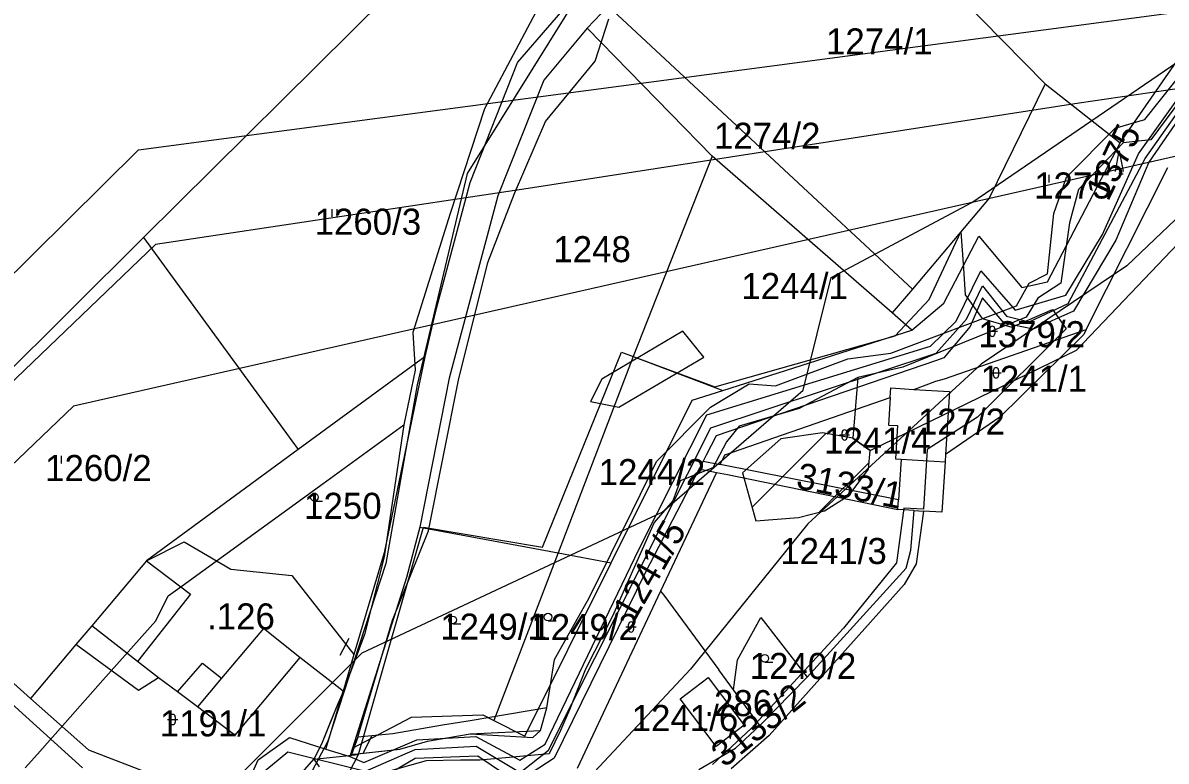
# Model space of a CAD drawing. Extents: x -564810 to -550519, y -1045831 to -1034011.
# Drawn here: x -554205.9 to -553982, y -1038887.8 to -1038743.2 of the extents above; entities that cross this region are included whole.
import ezdxf

# ---------------------------------------------------------------- set-up
doc = ezdxf.new("R2010")
doc.units = 0
for name, color, linetype in [('KN stav', 7, 'Continuous'), ('Lesní porost', 7, 'Continuous'), ('Obvod KPU', 7, 'Continuous'), ('Parcelní čísla', 7, 'Continuous'), ('Polní cesty stavající', 7, 'Continuous'), ('STG', 7, 'Continuous'), ('Vedení VN', 7, 'Continuous'), ('Vodní plocha', 7, 'Continuous'), ('vodní toky', 7, 'Continuous'), ('Vrstva 22', 7, 'Continuous'), ('Vrstva 33', 7, 'Continuous'), ('Vrstva 39', 7, 'Continuous'), ('Vrstva 4', 7, 'Continuous'), ('zamokř ploch', 7, 'Continuous')]:
    doc.layers.add(name, color=color, linetype=linetype)

msp = doc.modelspace()

# ---------------------------------------------------------------- linework, layer by layer
at = {"layer": 'KN stav'}
for p, q in [((-554056.62, -1038703.41), (-554005.71, -1038755.12)), ((-554115.3, -1038718.86), (-554182.27, -1038785.24)), ((-554099.39, -1038739.76), (-554109.03, -1038750.89)), ((-554091.3, -1038739.91), (-554095.38, -1038744.23)), ((-554091.3, -1038739.91), (-554031.72, -1038795.33)), ((-554095.38, -1038744.23), (-554103.88, -1038754.42)), ((-554095.38, -1038744.23), (-554070.95, -1038769.33)), ((-553987.46, -1038768.82), (-553971.66, -1038746.69)), ((-553969.78, -1038747.75), (-553985.45, -1038770.47)), ((-553991.06, -1038766.69), (-553978.32, -1038748.33)), ((-554109.03, -1038750.89), (-554118.37, -1038774.51)), ((-554103.88, -1038754.42), (-554112.89, -1038777.05)), ((-554005.71, -1038755.12), (-554016.72, -1038777.54)), ((-554005.71, -1038755.12), (-553991.06, -1038766.69)), ((-554005.27, -1038793.9), (-553991.06, -1038766.69)), ((-554070.95, -1038769.33), (-554086.39, -1038808.52)), ((-554035.67, -1038800.01), (-554070.95, -1038769.33)), ((-553994.51, -1038784.66), (-553987.46, -1038768.82)), ((-553997.71, -1038803.26), (-553981.71, -1038771.49)), ((-553985.45, -1038770.47), (-553991.92, -1038785.77)), ((-554118.37, -1038774.51), (-554125.24, -1038800.17)), ((-554112.89, -1038777.05), (-554122.41, -1038812.76)), ((-554016.72, -1038777.54), (-554031.72, -1038795.33)), ((-554182.27, -1038785.24), (-554239.98, -1038842.52)), ((-554182.27, -1038785.24), (-554151.98, -1038826.75)), ((-554025.55, -1038798.11), (-554018.7, -1038784.97)), ((-554018.7, -1038784.97), (-554010.3, -1038795.05)), ((-554001.65, -1038796.55), (-553994.51, -1038784.66)), ((-553991.92, -1038785.77), (-554000.2, -1038799.65)), ((-554023.15, -1038801.62), (-554018.35, -1038791.75)), ((-554018.35, -1038791.75), (-554011.58, -1038799.45)), ((-554010.3, -1038795.05), (-554005.27, -1038793.9)), ((-554031.72, -1038795.33), (-554035.67, -1038800.01)), ((-554018.03, -1038797.01), (-554020.4, -1038802.67)), ((-554013.75, -1038802.02), (-554018.03, -1038797.01)), ((-554011.58, -1038799.45), (-554001.65, -1038796.55)), ((-554031.82, -1038803.36), (-554025.55, -1038798.11)), ((-554125.24, -1038800.17), (-554127.21, -1038808.6)), ((-554031.82, -1038803.36), (-554035.67, -1038800.01)), ((-554028.15, -1038806.49), (-554023.15, -1038801.62)), ((-554000.2, -1038799.65), (-554008.1, -1038803.2)), ((-554068.84, -1038815.18), (-554031.82, -1038803.36)), ((-554020.4, -1038802.67), (-554025.54, -1038808.81)), ((-554025.44, -1038812.88), (-553997.71, -1038803.26)), ((-554008.1, -1038803.2), (-554013.75, -1038802.02)), ((-553997.71, -1038803.26), (-553998.18, -1038804.2)), ((-553998.18, -1038804.2), (-554014.59, -1038820.44)), ((-554071.99, -1038819.97), (-554028.15, -1038806.49)), ((-554127.21, -1038808.6), (-554151.98, -1038826.75)), ((-554127.21, -1038808.6), (-554135.17, -1038846.98)), ((-554086.39, -1038808.52), (-554101.09, -1038846.95)), ((-554086.39, -1038808.52), (-554071.04, -1038814.34)), ((-554027.18, -1038809.37), (-554070.14, -1038824.05)), ((-554025.54, -1038808.81), (-554027.18, -1038809.37)), ((-554122.41, -1038812.76), (-554128.16, -1038841.93)), ((-554071.04, -1038814.34), (-554068.84, -1038815.18)), ((-554036.08, -1038816.57), (-554035.96, -1038814.67)), ((-554035.96, -1038814.67), (-554031.43, -1038814.96)), ((-554031.43, -1038814.96), (-554027.12, -1038813.37)), ((-554031.43, -1038814.96), (-554024.46, -1038815.39)), ((-554027.12, -1038813.37), (-554025.44, -1038812.88)), ((-554090.71, -1038848.96), (-554074.85, -1038817.1)), ((-554074.85, -1038817.1), (-554068.84, -1038815.18)), ((-554068.47, -1038827.8), (-554036.08, -1038816.57)), ((-554036.08, -1038816.57), (-554036.41, -1038821.95)), ((-554024.46, -1038815.39), (-554025.23, -1038827.74)), ((-554085.24, -1038846.17), (-554071.99, -1038819.97)), ((-554014.59, -1038820.44), (-554025.23, -1038827.74)), ((-554036.41, -1038821.95), (-554034.66, -1038822.06)), ((-554034.66, -1038822.06), (-554035.06, -1038828.57)), ((-554070.14, -1038824.05), (-554072.1, -1038827.84)), ((-554151.98, -1038826.75), (-554181.72, -1038848.55)), ((-554072.1, -1038827.84), (-554072.71, -1038829.01)), ((-554069.35, -1038829.68), (-554068.81, -1038828.51)), ((-554068.81, -1038828.51), (-554068.47, -1038827.8)), ((-554025.23, -1038827.74), (-554025.32, -1038829.17)), ((-554073.51, -1038830.54), (-554084, -1038850.77)), ((-554072.71, -1038829.01), (-554073.51, -1038830.54)), ((-554073.51, -1038830.54), (-554070.08, -1038831.22)), ((-554072.71, -1038829.01), (-554069.35, -1038829.68)), ((-554034.45, -1038836.61), (-554069.35, -1038829.68)), ((-554035.06, -1038828.57), (-554033.95, -1038828.64)), ((-554033.95, -1038828.64), (-554034.45, -1038836.61)), ((-554025.32, -1038829.17), (-554025.94, -1038839.02)), ((-554070.08, -1038831.22), (-554081.02, -1038854.46)), ((-554070.08, -1038831.22), (-554067.92, -1038831.67)), ((-554067.92, -1038831.67), (-554034.57, -1038838.48)), ((-554034.57, -1038838.48), (-554034.45, -1038836.61)), ((-554031.41, -1038838.68), (-554034.57, -1038838.48)), ((-554032.03, -1038846.46), (-554031.41, -1038838.68)), ((-554031.41, -1038838.68), (-554029.52, -1038838.8)), ((-554029.52, -1038838.8), (-554030.96, -1038849.15)), ((-554025.94, -1038839.02), (-554029.52, -1038838.8)), ((-554128.16, -1038841.93), (-554130.76, -1038851.78)), ((-554128.16, -1038841.93), (-554101.09, -1038846.95)), ((-554181.72, -1038848.55), (-554174.32, -1038844.83)), ((-554174.32, -1038844.83), (-554165.18, -1038850.15)), ((-554103.63, -1038884.47), (-554085.24, -1038846.17)), ((-554204.4, -1038875.48), (-554235.79, -1038847.61)), ((-554181.72, -1038848.55), (-554192.42, -1038861.26)), ((-554135.17, -1038846.98), (-554141.08, -1038866.86)), ((-554101.09, -1038846.95), (-554113.67, -1038879.84)), ((-554101.09, -1038846.95), (-554090.71, -1038848.96)), ((-554032.94, -1038849.95), (-554032.03, -1038846.46)), ((-554165.18, -1038850.15), (-554153.21, -1038851.44)), ((-554107.59, -1038882.89), (-554090.71, -1038848.96)), ((-554084, -1038850.77), (-554101.9, -1038887.2)), ((-554052.35, -1038871.34), (-554032.94, -1038849.95)), ((-554030.96, -1038849.15), (-554033.32, -1038853.2)), ((-554194.26, -1038889.05), (-554234.09, -1038853.01)), ((-554153.21, -1038851.44), (-554141.08, -1038866.86)), ((-554130.76, -1038851.78), (-554141.34, -1038885.24)), ((-554081.02, -1038854.46), (-554097.39, -1038889.23)), ((-554081.02, -1038854.46), (-554080.41, -1038855.28)), ((-554080.41, -1038855.28), (-554069.64, -1038869.87)), ((-554033.32, -1038853.2), (-554059.74, -1038882.73)), ((-554065.97, -1038867.95), (-554061.41, -1038859.66)), ((-554061.41, -1038859.66), (-554052.35, -1038871.34)), ((-554192.42, -1038861.26), (-554195.52, -1038864.94)), ((-554195.52, -1038864.94), (-554204.4, -1038875.48)), ((-554183.24, -1038873.92), (-554195.52, -1038864.94)), ((-554151.68, -1038867.46), (-554164.4, -1038882.66)), ((-554143.21, -1038874.06), (-554151.68, -1038867.46)), ((-554141.08, -1038866.86), (-554143.21, -1038874.06)), ((-554066.75, -1038873.79), (-554065.97, -1038867.95)), ((-554066.75, -1038873.79), (-554069.64, -1038869.87)), ((-554179.33, -1038871.43), (-554183.24, -1038873.92)), ((-554175.64, -1038874.21), (-554179.33, -1038871.43)), ((-554077.23, -1038875.6), (-554071.73, -1038871.41)), ((-554071.73, -1038871.41), (-554066.27, -1038878.57)), ((-554061.59, -1038880.77), (-554052.35, -1038871.34)), ((-554204.4, -1038875.48), (-554193.06, -1038885.54)), ((-554171.74, -1038877.14), (-554175.64, -1038874.21)), ((-554145.69, -1038882.41), (-554143.21, -1038874.06)), ((-554065.89, -1038874.95), (-554066.75, -1038873.79)), ((-554061.59, -1038880.77), (-554065.89, -1038874.95)), ((-554164.4, -1038882.66), (-554171.74, -1038877.14)), ((-554070.15, -1038884.89), (-554077.23, -1038875.6)), ((-554141.34, -1038885.24), (-554129.83, -1038879.15)), ((-554129.83, -1038879.15), (-554115.87, -1038878.73)), ((-554115.87, -1038878.73), (-554113.67, -1038879.84)), ((-554113.67, -1038879.84), (-554107.59, -1038882.89)), ((-554066.27, -1038878.57), (-554064.65, -1038880.7)), ((-554064.65, -1038880.7), (-554070.15, -1038884.89)), ((-554066.34, -1038885.2), (-554061.59, -1038880.77)), ((-554159.84, -1038887.51), (-554153.7, -1038883.17)), ((-554153.7, -1038883.17), (-554146.58, -1038885.4)), ((-554146.58, -1038885.4), (-554145.69, -1038882.41)), ((-554139.17, -1038888.06), (-554128.76, -1038883.57)), ((-554128.76, -1038883.57), (-554117.23, -1038882.94)), ((-554117.23, -1038882.94), (-554108.58, -1038887.59)), ((-554108.58, -1038887.59), (-554103.63, -1038884.47)), ((-554059.74, -1038882.73), (-554067.21, -1038889.27)), ((-554193.06, -1038885.54), (-554174.16, -1038892.82)), ((-554146.58, -1038885.4), (-554141.86, -1038886.89)), ((-554141.34, -1038885.24), (-554141.86, -1038886.89)), ((-554073.53, -1038889.42), (-554066.34, -1038885.2)), ((-554163.92, -1038896.77), (-554159.84, -1038887.51)), ((-554141.86, -1038886.89), (-554139.17, -1038888.06)), ((-554129.08, -1038887.23), (-554136.6, -1038891.71)), ((-554116.79, -1038886.81), (-554129.08, -1038887.23)), ((-554109.21, -1038891.94), (-554116.79, -1038886.81)), ((-554101.9, -1038887.2), (-554109.21, -1038891.94))]:
    msp.add_line(p, q, dxfattribs=at)
at = {"layer": 'Lesní porost'}
for p, q in [((-553999.58, -1038807.28), (-553978.35, -1038785.04)), ((-554076.69, -1038803.57), (-554092.56, -1038812.99)), ((-554072.58, -1038808.69), (-554076.69, -1038803.57)), ((-554040.01, -1038826.97), (-553999.58, -1038807.28)), ((-554089.2, -1038818.43), (-554072.58, -1038808.69)), ((-554042.42, -1038812.67), (-554043.42, -1038824.52)), ((-554092.56, -1038812.99), (-554094.78, -1038817.36)), ((-554094.78, -1038817.36), (-554089.2, -1038818.43)), ((-554043.42, -1038824.52), (-554040.01, -1038826.97))]:
    msp.add_line(p, q, dxfattribs=at)
msp.add_lwpolyline([(-553977.33, -1038755.75), (-553985.02, -1038766.13), (-553990.47, -1038766.71), (-553999.18, -1038775.82), (-554000.99, -1038782.33), (-554002.66, -1038794.15), (-554007.15, -1038797.12), (-554009.45, -1038800.84), (-554033.61, -1038810.63), (-554042.42, -1038812.67)], dxfattribs=at)
at = {"layer": 'Obvod KPU'}
for p, q in [((-554028.43, -1038797.37), (-554022.24, -1038784.14)), ((-554022.24, -1038784.14), (-554021.75, -1038791.32)), ((-554021.75, -1038791.32), (-554021.39, -1038796.46)), ((-554021.39, -1038796.46), (-554018.05, -1038801.11)), ((-554035.1, -1038804.46), (-554028.43, -1038797.37)), ((-554012.28, -1038802.77), (-554004.27, -1038799.32)), ((-554004.27, -1038799.32), (-554001.64, -1038803.12)), ((-554018.05, -1038801.11), (-554012.28, -1038802.77)), ((-554001.64, -1038803.12), (-554018.95, -1038820.39)), ((-554070.38, -1038814.5), (-554035.1, -1038804.46)), ((-554104.14, -1038845.88), (-554088.68, -1038807.65)), ((-554088.68, -1038807.65), (-554070.38, -1038814.5)), ((-554018.95, -1038820.39), (-554028.84, -1038826.73)), ((-554147.1, -1038833.4), (-554131.32, -1038821.94)), ((-554131.32, -1038821.94), (-554135.18, -1038847.77)), ((-554028.84, -1038826.73), (-554029.54, -1038838.45)), ((-554174.74, -1038853.44), (-554147.1, -1038833.4)), ((-554033.42, -1038838.22), (-554034.81, -1038848.93)), ((-554029.54, -1038838.45), (-554033.42, -1038838.22)), ((-554139.14, -1038882.8), (-554127.43, -1038841.93)), ((-554127.43, -1038841.93), (-554104.14, -1038845.88)), ((-554135.18, -1038847.77), (-554139.01, -1038862.97)), ((-554034.81, -1038848.93), (-554045.21, -1038861.7)), ((-554177.43, -1038855.39), (-554174.74, -1038853.44)), ((-554179.9, -1038860.27), (-554177.43, -1038855.39)), ((-554190.24, -1038871.93), (-554179.9, -1038860.27)), ((-554045.21, -1038861.7), (-554063.32, -1038881.4)), ((-554139.01, -1038862.97), (-554142.18, -1038871.45)), ((-554203.05, -1038886.38), (-554190.24, -1038871.93)), ((-554142.18, -1038871.45), (-554143.18, -1038874.21)), ((-554143.18, -1038874.21), (-554144.22, -1038876.54)), ((-554144.22, -1038876.54), (-554145.74, -1038880.23)), ((-554145.74, -1038880.23), (-554147.43, -1038884.44)), ((-554063.32, -1038881.4), (-554070.89, -1038888.4)), ((-554147.43, -1038884.44), (-554148.93, -1038887.41)), ((-554140.2, -1038886.48), (-554139.14, -1038882.8)), ((-554205.48, -1038889.11), (-554203.05, -1038886.38)), ((-554148.93, -1038887.41), (-554140.2, -1038886.48))]:
    msp.add_line(p, q, dxfattribs=at)
at = {"layer": 'Polní cesty stavající'}
for p, q in [((-554103.28, -1038877.32), (-554118.31, -1038879.86)), ((-554118.31, -1038879.86), (-554123.73, -1038880.73)), ((-554123.73, -1038880.73), (-554133.45, -1038882.43)), ((-554118.3, -1038882.44), (-554104.55, -1038881.75)), ((-554140.3, -1038883.07), (-554141.58, -1038886.44)), ((-554137.58, -1038882.82), (-554140.3, -1038883.07)), ((-554137.58, -1038882.82), (-554139.3, -1038886.19)), ((-554139.3, -1038886.19), (-554137.58, -1038882.82)), ((-554133.45, -1038882.43), (-554137.58, -1038882.82)), ((-554132.11, -1038885.42), (-554126.66, -1038883.84)), ((-554126.66, -1038883.84), (-554118.3, -1038882.44))]:
    msp.add_line(p, q, dxfattribs=at)
for points in [[(-554104.55, -1038881.75), (-554103.28, -1038877.32)], [(-554141.58, -1038886.44), (-554139.3, -1038886.19)], [(-554139.3, -1038886.19), (-554132.11, -1038885.42)]]:
    msp.add_lwpolyline(points, dxfattribs=at)
at = {"layer": 'STG'}
for points in [[(-554297.47, -1039079.72), (-554218.48, -1038969.46), (-554174.39, -1038901.47), (-554139.48, -1038866.56), (-554080.7, -1038838.99), (-554053.14, -1038815.1), (-554047.63, -1038793.05), (-554020.07, -1038778.35), (-553979.66, -1038750.79), (-553961.29, -1038714.04), (-553933.73, -1038651.56), (-553906.17, -1038609.29), (-553874.94, -1038585.4), (-553836.36, -1038574.38), (-553801.46, -1038546.81), (-553750.02, -1038504.55), (-553677.45, -1038481.12)], [(-553611.32, -1038486.63), (-553648.06, -1038510.52), (-553714.2, -1038536.25), (-553770.23, -1038572.08), (-553806.97, -1038602.4), (-553821.67, -1038604.24), (-553853.81, -1038618.94), (-553908.93, -1038690.61), (-553953.02, -1038755.84), (-553989.76, -1038790.75), (-554018.24, -1038810.05), (-554052.22, -1038841.29), (-554075.19, -1038869.77), (-554115.6, -1038912.95), (-554136.73, -1038939.6), (-554198.27, -1039025.05), (-554249.71, -1039093.96), (-554296.56, -1039137.12)]]:
    msp.add_lwpolyline(points, dxfattribs=at)
at = {"layer": 'Vedení VN'}
msp.add_line((-554142.09, -1038863.74), (-554143.83, -1038867.07), dxfattribs=at)
for points in [[(-554311.13, -1038894.55), (-554183.26, -1038768.06), (-553948.71, -1038736.97), (-553887.24, -1038715.77), (-553721.22, -1038534.86), (-553615.96, -1038471.97), (-553583.46, -1038409.78), (-553495.15, -1038284), (-553204.09, -1037884.03), (-552966, -1037802.05), (-552952.58, -1037796.4), (-552903.13, -1037697.47), (-552835.31, -1037471.34), (-552755.48, -1037231.07), (-552629.72, -1036976.67), (-552323.11, -1036754.78)], [(-552318.17, -1036790.68), (-552611.35, -1036998.44), (-552747, -1037286.75), (-552886.17, -1037729.13), (-552939.86, -1037825.23), (-553193.49, -1037916.39), (-553506.46, -1038353.11), (-553565.8, -1038423.21), (-553601.83, -1038493.17), (-553700.74, -1038549.7), (-553878.06, -1038746.16), (-554195.97, -1038818.23), (-554311.84, -1038929.18)], [(-554096.68, -1038736.92), (-554118.94, -1038772.7), (-554128.71, -1038814.06), (-554134.81, -1038849.08)], [(-553948.23, -1038751.46), (-553999.04, -1038758.95), (-554106.94, -1038775.6), (-554179.91, -1038786.59), (-554240.95, -1038845.08), (-554307.77, -1038908.41)], [(-554134.81, -1038849.08), (-554146.16, -1038883.84), (-554162.32, -1038914.39), (-554176.33, -1038954.03)]]:
    msp.add_lwpolyline(points, dxfattribs=at)
at = {"layer": 'Vodní plocha'}
for p, q in [((-554063.14, -1038838.08), (-554048.67, -1038823.61)), ((-554049.3, -1038823.5), (-554057.47, -1038824.67)), ((-554043.42, -1038824.52), (-554049.3, -1038823.5)), ((-554057.47, -1038824.67), (-554065.02, -1038831.29)), ((-554040.01, -1038826.97), (-554043.42, -1038824.52)), ((-554040.31, -1038830.58), (-554040.01, -1038826.97)), ((-554049.9, -1038838.98), (-554040.2, -1038829.29)), ((-554044.12, -1038835.67), (-554040.31, -1038830.58)), ((-554065.02, -1038831.29), (-554062.41, -1038840.69)), ((-554048.95, -1038838.73), (-554044.12, -1038835.67)), ((-554054.04, -1038840.09), (-554048.95, -1038838.73)), ((-554062.41, -1038840.69), (-554054.04, -1038840.09))]:
    msp.add_line(p, q, dxfattribs=at)
at = {"layer": 'vodní toky'}
for points in [[(-554141.58, -1038886.44), (-554132.11, -1038885.42), (-554126.66, -1038883.84), (-554118.3, -1038882.44), (-554106.07, -1038883.15), (-554104.55, -1038881.75), (-554103.28, -1038877.32), (-554101.79, -1038867.87), (-554095.02, -1038855.79), (-554086.56, -1038838.66), (-554081.85, -1038829.08), (-554071.27, -1038818.46), (-554063.69, -1038813.86), (-554058.54, -1038814.3), (-554044.36, -1038809), (-554035.94, -1038807.89), (-554011.35, -1038798.6), (-554008.83, -1038794.16), (-554005.25, -1038792.31), (-554004.04, -1038780.54), (-554001.57, -1038773.38), (-553992.03, -1038763.84), (-553986.2, -1038762.14), (-553974.72, -1038747.66)], [(-553972.61, -1038749.38), (-553985.02, -1038766.13), (-553990.47, -1038766.71), (-553999.18, -1038775.82), (-554000.99, -1038782.33), (-554002.66, -1038794.15), (-554007.15, -1038797.12), (-554009.45, -1038800.84), (-554033.61, -1038810.63), (-554042.42, -1038812.67), (-554053.89, -1038818.74), (-554065.64, -1038822.17), (-554068.12, -1038825.23), (-554070.83, -1038830.33), (-554077.18, -1038832.91), (-554078.62, -1038836.79), (-554082.29, -1038841.03), (-554090.42, -1038859.35), (-554095.73, -1038869.78), (-554098.84, -1038877.74), (-554100.65, -1038881.77), (-554102.85, -1038886.33), (-554116.44, -1038887.61), (-554120.21, -1038887.61), (-554126.94, -1038887.74), (-554135.56, -1038890.15)], [(-554173.25, -1038931.95), (-554170.3, -1038926.03), (-554169.73, -1038924.16), (-554165.7, -1038911.82), (-554163.73, -1038908.98), (-554161.87, -1038905.81), (-554158.41, -1038898.23), (-554148.93, -1038887.41), (-554147.87, -1038888.88)]]:
    msp.add_lwpolyline(points, dxfattribs=at)
at = {"layer": 'Vrstva 33'}
msp.add_lwpolyline([(-554159.66, -1038890.61), (-554154.01, -1038885.97), (-554138.8, -1038889.74), (-554129.09, -1038885.5), (-554117.17, -1038884.85), (-554108.55, -1038889.99), (-554102.97, -1038885.64), (-554071.21, -1038822.53), (-554027.07, -1038807.85), (-554021.13, -1038801.25), (-554018.01, -1038794.66), (-554013.3, -1038800.6), (-554008.88, -1038801.76), (-554001.2, -1038798.17), (-553986.14, -1038769.76), (-553970.58, -1038747.77)], dxfattribs=at)
at = {"layer": 'Vrstva 39'}
for points in [[(-554029.29, -1038651.87), (-554072.58, -1038704.89), (-554094.74, -1038731.99), (-554102.1, -1038734.61), (-554115.51, -1038760.06), (-554122.25, -1038780.51), (-554129.57, -1038803.8), (-554129.11, -1038811.18), (-554131.32, -1038821.94), (-554135.18, -1038847.77), (-554139.01, -1038862.97), (-554143.18, -1038874.21), (-554144.22, -1038876.54), (-554147.43, -1038884.44), (-554148.93, -1038887.41), (-554147.87, -1038888.88)], [(-554142.9, -1038891.74), (-554140.2, -1038886.48), (-554141.58, -1038886.44), (-554140.3, -1038883.07), (-554133.53, -1038860.14), (-554126.48, -1038842.69), (-554120.6, -1038813.19), (-554114.84, -1038790.09), (-554109.67, -1038776.6), (-554103.54, -1038762.51), (-554093.82, -1038750.69), (-554091.2, -1038742.38)]]:
    msp.add_lwpolyline(points, dxfattribs=at)
at = {"layer": 'Vrstva 4'}
for p, q in [((-554033.95, -1038828.63), (-554025.32, -1038829.17)), ((-554181.72, -1038848.55), (-554173.1, -1038855.09)), ((-554173.1, -1038855.09), (-554183.44, -1038868.23)), ((-554183.44, -1038868.23), (-554192.43, -1038861.26)), ((-554158.82, -1038861.79), (-554167, -1038871.51)), ((-554151.68, -1038867.45), (-554158.82, -1038861.79)), ((-554179.33, -1038871.43), (-554183.44, -1038868.23)), ((-554175.64, -1038874.2), (-554170.72, -1038868.56)), ((-554170.72, -1038868.56), (-554167, -1038871.51)), ((-554167, -1038871.51), (-554171.74, -1038877.13))]:
    msp.add_line(p, q, dxfattribs=at)
at = {"layer": 'zamokř ploch'}
for p, q in [((-554005.99, -1038772.98), (-554005.99, -1038774.48)), ((-554004.99, -1038772.98), (-554004.99, -1038774.48)), ((-554145.41, -1038779.7), (-554145.41, -1038781.2)), ((-554144.41, -1038779.7), (-554144.41, -1038781.2)), ((-554017.08, -1038803.59), (-554015.08, -1038803.59)), ((-554016.58, -1038803.09), (-554016.58, -1038804.09)), ((-554015.58, -1038803.09), (-554015.58, -1038804.09)), ((-554016.35, -1038811.73), (-554014.35, -1038811.73)), ((-554015.85, -1038812.23), (-554015.85, -1038811.23)), ((-554014.85, -1038811.23), (-554014.85, -1038812.23)), ((-554046.01, -1038823.89), (-554044.01, -1038823.89)), ((-554045.51, -1038824.39), (-554045.51, -1038823.39)), ((-554044.51, -1038823.39), (-554044.51, -1038824.39)), ((-554199.42, -1038827.99), (-554199.42, -1038829.49)), ((-554198.42, -1038827.99), (-554198.42, -1038829.49)), ((-554148.82, -1038836.83), (-554147.22, -1038836.83)), ((-554121.74, -1038860.87), (-554120.15, -1038860.87)), ((-554103.08, -1038860.32), (-554101.48, -1038860.32)), ((-554087.82, -1038861.49), (-554085.82, -1038861.49)), ((-554087.32, -1038861.99), (-554087.32, -1038860.99)), ((-554086.32, -1038860.99), (-554086.32, -1038861.99)), ((-554060.64, -1038868.39), (-554059.04, -1038868.39)), ((-554177.58, -1038879.61), (-554175.58, -1038879.61)), ((-554177.08, -1038879.11), (-554177.08, -1038880.11)), ((-554176.08, -1038879.11), (-554176.08, -1038880.11))]:
    msp.add_line(p, q, dxfattribs=at)
for points in [[(-553991.94, -1038772.27), (-553991.24, -1038768.27), (-553990.44, -1038772.27)], [(-553991.24, -1038772.57), (-553991.24, -1038772.77), (-553990.44, -1038772.77)]]:
    msp.add_lwpolyline(points, dxfattribs=at)
for centre in [(-554148.82, -1038836.08), (-554121.74, -1038860.12), (-554103.08, -1038859.57), (-554060.64, -1038867.64)]:
    msp.add_circle(centre, 0.75, dxfattribs=at)
for centre, start, end in [((-554016.09, -1038803.09), 0, 180), ((-554016.09, -1038804.09), 180, 0), ((-554015.35, -1038811.23), 0, 180), ((-554015.35, -1038812.23), 180, 0), ((-554045.01, -1038823.39), 0, 180), ((-554045.01, -1038824.39), 180, 0), ((-554086.82, -1038860.99), 0, 180), ((-554086.82, -1038861.99), 180, 0), ((-554176.58, -1038879.12), 0, 180), ((-554176.58, -1038880.12), 180, 0)]:
    msp.add_arc(centre, 0.5, start, end, dxfattribs=at)

# ---------------------------------------------------------------- texts
at = {"layer": 'Parcelní čísla'}
for s, p in [('1274/1', (-554048.64, -1038749.38)), ('1274/2', (-554070.6, -1038767.86)), ('1275', (-554007.88, -1038777.59)), ('1260/3', (-554148.78, -1038784.68)), ('1248', (-554102.03, -1038790.06)), ('1244/1', (-554065.22, -1038797.28)), ('1379/2', (-554018.8, -1038806.71)), ('1241/1', (-554018.39, -1038815.44)), ('1241/4', (-554049.03, -1038827.55)), ('1260/2', (-554201.55, -1038832.92)), ('1244/2', (-554093.16, -1038833.72)), ('1250', (-554150.83, -1038840.32)), ('1241/3', (-554057.6, -1038849.17)), ('1249/1', (-554124.18, -1038863.98)), ('1249/2', (-554106.34, -1038864.06)), ('1240/2', (-554063.58, -1038871.68)), ('1191/1', (-554179.09, -1038882.92)), ('1241/6', (-554086.69, -1038881.87))]:
    msp.add_text(s, height=5.1, dxfattribs=at).set_placement(p)
for s, rotation, p in [('1375', 64.2741, (-553993.39, -1038778.33)), ('3133/1', 348.5544, (-554054.71, -1038834.24)), ('1241/5', 60.2478, (-554086.21, -1038860.66)), ('3133/2', 38.6198, (-554068.53, -1038889.17))]:
    msp.add_text(s, height=5.1, rotation=rotation, dxfattribs=at).set_placement(p)
at = {"layer": 'Vrstva 22'}
for s, p in [('.127/2', (-554032.55, -1038823.83)), ('.126', (-554169.84, -1038861.98)), ('.286', (-554072.47, -1038878.96))]:
    msp.add_text(s, height=5.1, dxfattribs=at).set_placement(p)

doc.saveas('drawing.dxf')
